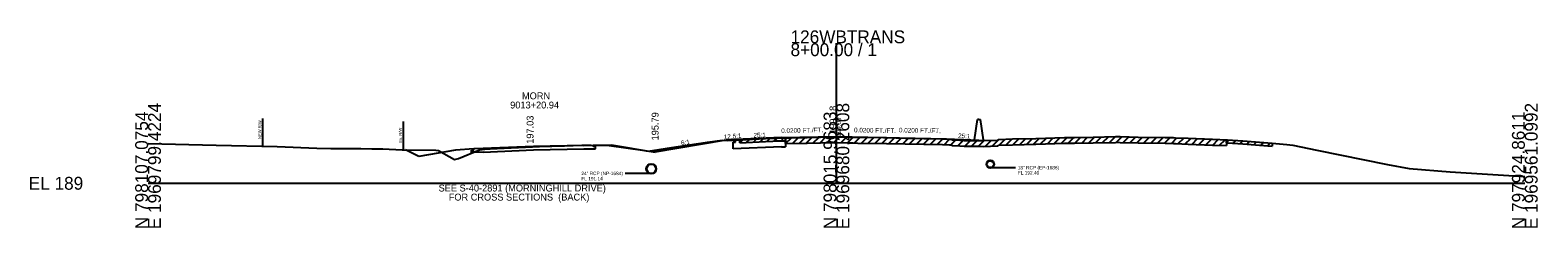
# Model space of a CAD drawing. Extents: x -6494 to 1970605, y -10 to 798140.
# Drawn here: x -25.7 to 302.8, y 490.3 to 533.3 of the extents above; entities that cross this region are included whole.
import ezdxf

# ---------------------------------------------------------------- set-up
doc = ezdxf.new("R2010")
doc.units = 0
for name, color, linetype in [('RD_GPK_XS_Cell', 7, 'Continuous'), ('RD_XS_Base', 7, 'Continuous'), ('RD_XS_EarthShd', 7, 'Continuous'), ('RD_XS_ExGround', 7, 'Continuous'), ('RD_XS_ExPaveRet', 7, 'Continuous'), ('RD_XS_ExRW', 7, 'Continuous'), ('RD_XS_MedBWall', 7, 'Continuous'), ('RD_XS_Misc_Line', 7, 'Continuous'), ('RD_XS_NewRW', 7, 'Continuous'), ('RD_XS_Pave', 7, 'Continuous'), ('RD_XS_PaveOvlay', 7, 'Continuous'), ('RD_XS_PaveShd', 7, 'Continuous'), ('RD_XS_Pipe', 7, 'Continuous'), ('RD_XS_TieSlope', 7, 'Continuous'), ('RD_XS_TX_Elev_EX', 7, 'Continuous'), ('RD_XS_TX_Elev_PR', 7, 'Continuous'), ('RD_XS_TX_Misc', 7, 'Continuous'), ('RD_XS_TX_Notes', 7, 'Continuous'), ('RD_XS_TX_Profile', 7, 'Continuous'), ('RD_XS_TX_ShdSlope', 7, 'Continuous'), ('RD_XS_TX_Slope', 7, 'Continuous'), ('RD_XS_TX_Station', 7, 'Continuous')]:
    doc.layers.add(name, color=color, linetype=linetype)

msp = doc.modelspace()

# ---------------------------------------------------------------- linework, layer by layer
at = {"layer": 'RD_GPK_XS_Cell'}
for p, q in [((150, 500), (150, 530.47)), ((0, 500), (150, 500)), ((150, 500), (300, 500))]:
    msp.add_line(p, q, dxfattribs=at)
at = {"layer": 'RD_XS_Base'}
for p, q in [((128, 508.98), (128, 509.54)), ((70.49, 507.18), (70.99, 507.2)), ((70.49, 506.7), (70.49, 507.18)), ((72.99, 506.8), (70.49, 506.7)), ((70.99, 507.2), (70.99, 507.5)), ((94.99, 507.47), (97.49, 507.52)), ((96.99, 507.99), (96.99, 508.29)), ((97.49, 508), (96.99, 507.99)), ((97.49, 507.52), (97.49, 508)), ((127.5, 508.96), (128, 508.98)), ((127.5, 507.48), (127.5, 508.96)), ((138, 507.9), (127.5, 507.48)), ((138, 507.9), (138.93, 507.92))]:
    msp.add_line(p, q, dxfattribs=at)
at = {"layer": 'RD_XS_EarthShd'}
for p, q in [((128, 509.54), (126, 509.38)), ((70.99, 507.5), (66.99, 507.18)), ((96.99, 508.29), (100.99, 508.37))]:
    msp.add_line(p, q, dxfattribs=at)
at = {"layer": 'RD_XS_ExGround'}
msp.add_lwpolyline([(0, 508.69), (14.83, 508.28), (28.11, 508), (36.8, 507.67), (39.83, 507.6), (40.3, 507.6), (42.43, 507.59), (43.52, 507.57), (46.39, 507.55), (48.77, 507.52), (49.46, 507.51), (51.17, 507.48), (55.37, 507.31), (62.68, 507.18), (63.28, 507.16), (66.79, 505.2), (67.61, 505.4), (72.2, 507.28), (73.95, 507.46), (74.55, 507.49), (85.31, 508.01), (90.75, 508.17), (94.54, 508.27), (96.55, 508.29), (100.49, 508.25), (107.77, 507.23), (108.94, 507.01), (114.99, 507.91), (121.89, 508.98), (125.07, 509.35), (126.32, 509.33), (127.7, 509.38), (128.92, 509.46), (134.53, 509.74), (136.16, 509.81), (136.82, 509.83), (143.61, 509.99), (146.56, 510.05), (149, 510.1), (150, 510.09), (152.82, 510.04), (153.64, 510.02), (154.66, 510.01), (160.88, 509.94), (165.01, 509.84), (173.12, 509.66), (174.63, 509.61), (175.03, 509.59), (175.28, 509.48), (176.91, 509.37), (177.81, 509.31), (179.3, 509.3), (180.92, 509.29), (181.97, 509.28), (185.17, 509.4), (185.42, 509.52), (188.39, 509.65), (193.42, 509.78), (199.69, 509.95), (201.91, 509.99), (205.97, 510.05), (210.82, 510.15), (211.39, 510.16), (211.82, 510.15), (215.74, 510.05), (221.65, 509.96), (223.43, 509.94), (223.91, 509.91), (226.66, 509.79), (231.97, 509.57), (235.21, 509.44), (238.56, 509.2), (244.96, 508.74), (248.11, 508.41), (249.46, 508.27), (254.67, 507.22), (270.07, 504.09), (274.83, 503.2), (283.75, 502.52), (300, 501.5)], dxfattribs=at)
at = {"layer": 'RD_XS_ExPaveRet'}
for p, q in [((128.92, 508.83), (128.92, 509.46)), ((136.82, 509.21), (138.93, 509.26)), ((138.93, 508.63), (138.93, 509.88)), ((138.93, 509.88), (138.93, 509.26)), ((234.96, 509.45), (234.96, 508.2)), ((234.96, 508.83), (234.96, 509.45)), ((128.92, 508.83), (134.53, 509.11)), ((134.53, 509.11), (136.16, 509.19)), ((136.16, 509.19), (136.82, 509.21)), ((138.93, 508.63), (143.61, 508.74)), ((143.61, 508.74), (146.56, 508.8)), ((146.56, 508.8), (149, 508.85)), ((149, 508.85), (150, 508.84)), ((150, 508.84), (152.82, 508.79)), ((152.82, 508.79), (153.64, 508.77)), ((153.64, 508.77), (154.66, 508.76)), ((154.66, 508.76), (160.88, 508.69)), ((160.88, 508.69), (165.01, 508.59)), ((165.01, 508.59), (173.12, 508.41)), ((173.12, 508.41), (174.63, 508.36)), ((174.63, 508.36), (175.03, 508.34)), ((175.03, 508.34), (175.28, 508.23)), ((175.28, 508.23), (176.91, 508.12)), ((176.91, 508.12), (177.81, 508.06)), ((177.81, 508.06), (179.3, 508.05)), ((179.3, 508.05), (180.92, 508.04)), ((180.92, 508.04), (181.97, 508.03)), ((181.97, 508.03), (185.17, 508.15)), ((185.17, 508.15), (185.42, 508.27)), ((185.42, 508.27), (188.39, 508.4)), ((188.39, 508.4), (193.42, 508.53)), ((193.42, 508.53), (199.69, 508.7)), ((199.69, 508.7), (201.91, 508.74)), ((201.91, 508.74), (205.97, 508.8)), ((205.97, 508.8), (210.82, 508.9)), ((210.82, 508.9), (211.39, 508.91)), ((211.39, 508.91), (211.82, 508.9)), ((211.82, 508.9), (215.74, 508.8)), ((215.74, 508.8), (221.65, 508.71)), ((221.65, 508.71), (223.43, 508.69)), ((223.43, 508.69), (223.91, 508.66)), ((223.91, 508.66), (226.66, 508.54)), ((226.66, 508.54), (231.97, 508.32)), ((231.97, 508.32), (234.96, 508.2)), ((234.96, 508.83), (235.21, 508.82)), ((235.21, 508.82), (238.56, 508.58)), ((238.56, 508.58), (244.96, 508.11)), ((244.96, 508.74), (244.96, 508.11))]:
    msp.add_line(p, q, dxfattribs=at)
at = {"layer": 'RD_XS_ExRW'}
msp.add_line((55.57, 513.42), (55.57, 507.42), dxfattribs=at)
at = {"layer": 'RD_XS_MedBWall'}
for p, q in [((180.06, 509.43), (180.73, 513.91)), ((181.06, 513.91), (180.73, 513.91)), ((181.06, 513.91), (181.39, 513.91)), ((182.06, 509.43), (181.39, 513.91))]:
    msp.add_line(p, q, dxfattribs=at)
at = {"layer": 'RD_XS_Misc_Line'}
for p, q in [((128.92, 508.83), (129.58, 509.49)), ((130.42, 508.91), (131.08, 509.56)), ((131.92, 508.98), (132.58, 509.64)), ((133.42, 509.06), (134.08, 509.71)), ((134.92, 509.13), (135.58, 509.79)), ((136.42, 509.2), (137.07, 509.84)), ((137.93, 509.23), (138.57, 509.87)), ((138.93, 508.63), (140.21, 509.91)), ((140.43, 508.67), (141.71, 509.95)), ((141.93, 508.7), (143.21, 509.98)), ((143.43, 508.74), (144.71, 510.01)), ((144.93, 508.77), (146.21, 510.04)), ((146.43, 508.8), (147.71, 510.08)), ((147.93, 508.83), (149.2, 510.1)), ((149.43, 508.85), (150.66, 510.08)), ((150.94, 508.82), (152.17, 510.05)), ((152.44, 508.8), (153.67, 510.02)), ((153.94, 508.77), (155.17, 510.01)), ((155.44, 508.75), (156.67, 509.99)), ((156.94, 508.73), (158.18, 509.97)), ((158.44, 508.72), (159.68, 509.95)), ((159.94, 508.7), (161.17, 509.93)), ((161.44, 508.67), (162.67, 509.9)), ((162.94, 508.64), (164.17, 509.86)), ((164.45, 508.61), (165.67, 509.83)), ((165.95, 508.57), (167.17, 509.79)), ((167.45, 508.54), (168.67, 509.76)), ((168.95, 508.5), (170.17, 509.73)), ((170.45, 508.47), (171.67, 509.69)), ((171.95, 508.44), (173.17, 509.66)), ((173.45, 508.4), (174.66, 509.61)), ((174.95, 508.35), (176.04, 509.43)), ((176.45, 508.15), (177.63, 509.33)), ((177.96, 508.06), (179.2, 509.31)), ((179.46, 508.05), (180.7, 509.29)), ((180.96, 508.04), (182.21, 509.29)), ((182.46, 508.05), (183.76, 509.35)), ((183.96, 508.1), (185.34, 509.48)), ((185.46, 508.27), (186.77, 509.58)), ((186.96, 508.33), (188.27, 509.64)), ((188.46, 508.4), (189.75, 509.68)), ((189.96, 508.44), (191.25, 509.72)), ((191.47, 508.48), (192.75, 509.76)), ((192.97, 508.52), (194.25, 509.8)), ((194.47, 508.56), (195.75, 509.85)), ((195.97, 508.6), (197.25, 509.89)), ((197.47, 508.64), (198.76, 509.93)), ((198.97, 508.68), (200.25, 509.96)), ((200.47, 508.72), (201.74, 509.99)), ((201.97, 508.74), (203.24, 510.01)), ((203.47, 508.76), (204.74, 510.03)), ((204.98, 508.79), (206.25, 510.06)), ((206.48, 508.81), (207.75, 510.09)), ((207.98, 508.84), (209.25, 510.12)), ((209.48, 508.87), (210.75, 510.14)), ((210.98, 508.9), (212.22, 510.14)), ((212.48, 508.88), (213.7, 510.1)), ((213.98, 508.84), (215.2, 510.06)), ((215.48, 508.81), (216.71, 510.04)), ((216.98, 508.78), (218.22, 510.01)), ((218.49, 508.76), (219.72, 509.99)), ((219.99, 508.74), (221.22, 509.97)), ((221.49, 508.72), (222.72, 509.95)), ((222.99, 508.69), (224.2, 509.9)), ((224.49, 508.64), (225.69, 509.84)), ((225.99, 508.57), (227.19, 509.77)), ((227.49, 508.51), (228.69, 509.71)), ((228.99, 508.45), (230.19, 509.65)), ((230.49, 508.38), (231.7, 509.58)), ((232, 508.32), (233.2, 509.52)), ((233.5, 508.26), (234.7, 509.46)), ((234.96, 508.83), (235.55, 509.42)), ((236.46, 508.73), (237.04, 509.31)), ((237.96, 508.62), (238.54, 509.2)), ((239.46, 508.51), (240.04, 509.1)), ((240.96, 508.4), (241.55, 508.99)), ((242.46, 508.29), (243.05, 508.88)), ((243.96, 508.18), (244.55, 508.77))]:
    msp.add_line(p, q, dxfattribs=at)
at = {"layer": 'RD_XS_NewRW'}
msp.add_line((24.91, 514.07), (24.91, 508.07), dxfattribs=at)
at = {"layer": 'RD_XS_Pave'}
for p, q in [((138, 509.94), (150, 510.18)), ((150, 510.18), (174, 509.7)), ((83.99, 508.03), (72.99, 507.58)), ((72.99, 506.8), (83.99, 507.25)), ((94.99, 508.25), (83.99, 508.03)), ((83.99, 507.25), (94.99, 507.47))]:
    msp.add_line(p, q, dxfattribs=at)
at = {"layer": 'RD_XS_PaveOvlay'}
for p, q in [((138.93, 509.88), (143.61, 509.99)), ((138.93, 509.88), (138.93, 507.92)), ((143.61, 509.99), (146.56, 510.05)), ((146.56, 510.05), (149, 510.1)), ((149, 510.1), (150, 510.09)), ((150, 510.09), (152.82, 510.04)), ((152.82, 510.04), (153.64, 510.02)), ((153.64, 510.02), (154.66, 510.01)), ((154.66, 510.01), (160.88, 509.94)), ((160.88, 509.94), (165.01, 509.84)), ((165.01, 509.84), (173.12, 509.66)), ((173.12, 509.66), (174.63, 509.61)), ((174.63, 509.61), (175.03, 509.59)), ((175.03, 509.59), (175.28, 509.48)), ((175.28, 509.48), (176.91, 509.37)), ((176.91, 509.37), (177.81, 509.31)), ((177.81, 509.31), (179.3, 509.3)), ((179.3, 509.3), (180.92, 509.29)), ((180.92, 509.29), (181.06, 509.29))]:
    msp.add_line(p, q, dxfattribs=at)
at = {"layer": 'RD_XS_PaveShd'}
for p, q in [((138, 509.94), (128, 509.54)), ((174, 509.7), (181.06, 509.41)), ((181.06, 509.29), (181.06, 509.41)), ((72.99, 507.58), (70.99, 507.5)), ((94.99, 508.25), (96.99, 508.29))]:
    msp.add_line(p, q, dxfattribs=at)
at = {"layer": 'RD_XS_Pipe'}
for p, q in [((184.02, 503.4), (189.02, 503.4)), ((108.99, 502.14), (103.99, 502.14))]:
    msp.add_line(p, q, dxfattribs=at)
for centre, radius in [((109.65, 503.14), 1.1), ((109.65, 503.14), 1), ((183.52, 504.15), 0.85), ((183.52, 504.15), 0.75)]:
    msp.add_circle(centre, radius, dxfattribs=at)
at = {"layer": 'RD_XS_TieSlope'}
for p, q in [((126, 509.38), (110.49, 506.79)), ((58.98, 505.85), (56.09, 507.3)), ((66.99, 507.18), (58.98, 505.85)), ((100.99, 508.37), (110.49, 506.79)), ((110.49, 506.79), (110.49, 507.24))]:
    msp.add_line(p, q, dxfattribs=at)

# ---------------------------------------------------------------- texts
at = {"layer": 'RD_GPK_XS_Cell'}
for s, p in [('126WBTRANS', (140, 530.47)), ('8+00.00 / 1', (140, 527.67)), ('EL 189', (-26, 498.6))]:
    msp.add_text(s, height=2.8, dxfattribs=at).set_placement(p)
for s, p in [('E 1969799.4224', (2.8, 490)), ('E 1969680.2608', (152.8, 490)), ('E 1969561.0992', (302.8, 490)), ('N 798107.0754', (0, 490)), ('N 798015.9683', (150, 490)), ('N 797924.8611', (300, 490))]:
    msp.add_text(s, height=2.8, rotation=90, dxfattribs=at).set_placement(p)
at = {"layer": 'RD_XS_ExRW'}
msp.add_text('Ex. R/W ', height=0.65, rotation=90, dxfattribs=at).set_placement((55.32, 508.8))
at = {"layer": 'RD_XS_NewRW'}
msp.add_text('NEW R/W ', height=0.65, rotation=90, dxfattribs=at).set_placement((24.65, 509.63))
at = {"layer": 'RD_XS_Pipe'}
for s, p in [('18" RCP (EP-1686)', (189.52, 503.03)), ('FL 192.40', (189.52, 501.9)), ('24" RCP (NP-1684)', (94.42, 501.77)), ('FL 191.14', (94.42, 500.64))]:
    msp.add_text(s, height=0.75, dxfattribs=at).set_placement(p)
at = {"layer": 'RD_XS_TX_Elev_EX'}
msp.add_text('199.09', height=1, rotation=90, dxfattribs=at).set_placement((151, 510.09))
at = {"layer": 'RD_XS_TX_Elev_PR'}
for s, p in [(' 199.18', (150, 510.18)), (' 197.03', (83.99, 508.03))]:
    msp.add_text(s, height=1.5, rotation=90, dxfattribs=at).set_placement(p)
at = {"layer": 'RD_XS_TX_Misc'}
msp.add_text('195.79', height=1.5, rotation=90, dxfattribs=at).set_placement((111.24, 509.32))
at = {"layer": 'RD_XS_TX_Notes'}
for s, p in [('SEE S-40-2891 (MORNINGHILL DRIVE)', (63.31, 498.21)), ('FOR CROSS SECTIONS  (BACK)', (65.52, 496.24))]:
    msp.add_text(s, height=1.5, dxfattribs=at).set_placement(p)
at = {"layer": 'RD_XS_TX_Profile'}
for rotation, p in [(2.2906, (131.94, 509.94)), (357.7094, (176.49, 509.85))]:
    msp.add_text('25:1', height=1, rotation=rotation, dxfattribs=at).set_placement(p)
at = {"layer": 'RD_XS_TX_ShdSlope'}
msp.add_text('12.5:1', height=1, rotation=4.5739, dxfattribs=at).set_placement((125.5, 509.59))
at = {"layer": 'RD_XS_TX_Slope'}
for s, rotation, p in [('6:1', 9.4623, (116.22, 508.25)), ('0.0200 FT./FT.', 1.1458, (137.98, 510.94)), ('0.0200 FT./FT.', 358.8542, (153.83, 511.1)), ('0.0200 FT./FT.', 358.8542, (163.61, 511.08))]:
    msp.add_text(s, height=1, rotation=rotation, dxfattribs=at).set_placement(p)
at = {"layer": 'RD_XS_TX_Station'}
for s, p in [('MORN', (81.48, 518.28)), ('9013+20.94', (78.91, 516.28))]:
    msp.add_text(s, height=1.5, dxfattribs=at).set_placement(p)

doc.saveas('drawing.dxf')
